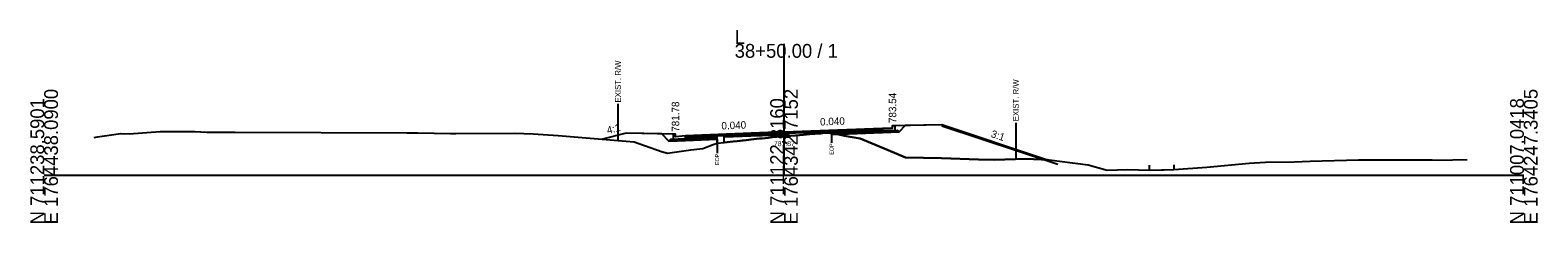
# Model space of a CAD drawing. Extents: x -26 to 5303, y -10 to 9578.
# Drawn here: x 1997.2 to 2302.8, y 8490.3 to 8529.4 of the extents above; entities that cross this region are included whole.
import ezdxf

# ---------------------------------------------------------------- set-up
doc = ezdxf.new("R2010")
doc.units = 0
for name, color, linetype in [('Default', 7, 'Continuous'), ('Exist CMT Pavement', 7, 'Continuous'), ('Exist Cross Section Cell', 7, 'Continuous'), ('Exist XS Ground Line', 7, 'Continuous'), ('Old_Level_10', 7, 'Continuous'), ('Old_Level_3', 7, 'Continuous'), ('Old_Level_4', 7, 'Continuous'), ('Prop CMT Conc Surface', 7, 'Continuous'), ('Prop CMT Concrete Structures', 7, 'Continuous'), ('Prop CMT Pvmt Course 1', 7, 'Continuous'), ('Prop CMT Pvmt Course 1 CG', 7, 'Continuous'), ('Prop CMT Pvmt Course 2', 7, 'Continuous'), ('Prop CMT Pvmt Course 3', 7, 'Continuous'), ('Prop CMT Pvmt Surface', 7, 'Continuous'), ('Prop CMT Slope Grass', 7, 'Continuous'), ('Prop CMT Subgrade Earthwork', 7, 'Continuous'), ('Prop XS Earthwork Shape', 7, 'Continuous'), ('Prop XS EOT Tick Mark', 7, 'Continuous'), ('Prop XS Hydro Elevations', 7, 'Continuous'), ('Prop XS SE Text', 7, 'Continuous'), ('Prop XS Side Slope Text', 7, 'Continuous'), ('Prop XS Wedging', 7, 'Continuous')]:
    doc.layers.add(name, color=color, linetype=linetype)

msp = doc.modelspace()

# ---------------------------------------------------------------- linework, layer by layer
at = {"layer": 'Exist CMT Pavement'}
msp.add_lwpolyline([(2136.43, 8506.48), (2137.88, 8506.63), (2139.72, 8506.82), (2140.51, 8506.9), (2141.5, 8507.02), (2142.31, 8507.11), (2143.27, 8507.21), (2144.44, 8507.34), (2145.05, 8507.4), (2145.55, 8507.45), (2146.83, 8507.58), (2147.68, 8507.68), (2148.48, 8507.76), (2150, 8507.87), (2150.38, 8507.9), (2152.3, 8508.05), (2153.93, 8508.18), (2155.27, 8508.29), (2155.71, 8508.33), (2156.24, 8508.36), (2157.48, 8508.45), (2157.84, 8508.48), (2159.24, 8508.57), (2159.65, 8508.58), (2159.65, 8508.58)], dxfattribs=at)
at = {"layer": 'Exist Cross Section Cell'}
for p, q in [((2150, 8500), (2150, 8526.59)), ((2000, 8500), (2150, 8500)), ((2150, 8500), (2300, 8500))]:
    msp.add_line(p, q, dxfattribs=at)
at = {"layer": 'Exist XS Ground Line'}
msp.add_lwpolyline([(2010.11, 8507.65), (2010.8, 8507.76), (2015.52, 8508.4), (2017.21, 8508.36), (2023.49, 8508.86), (2030.58, 8508.84), (2032.99, 8508.72), (2033.99, 8508.71), (2034.79, 8508.71), (2038.73, 8508.73), (2073.53, 8508.55), (2075.77, 8508.58), (2082.41, 8508.45), (2083.44, 8508.45), (2095.37, 8508.47), (2099.17, 8508.35), (2104.19, 8508.05), (2113.92, 8507.22), (2119.64, 8506.75), (2125.16, 8504.79), (2126.36, 8504.41), (2131.1, 8505.12), (2133.56, 8505.38), (2135.63, 8506.18), (2136.43, 8506.48), (2137.88, 8506.63), (2139.72, 8506.82), (2140.51, 8506.9), (2142.31, 8507.11), (2144.44, 8507.34), (2145.05, 8507.4), (2145.55, 8507.45), (2146.83, 8507.58), (2147.68, 8507.68), (2148.48, 8507.76), (2150, 8507.87), (2150.38, 8507.9), (2152.3, 8508.05), (2155.27, 8508.29), (2155.71, 8508.33), (2156.24, 8508.36), (2157.48, 8508.45), (2157.84, 8508.48), (2159.24, 8508.57), (2159.65, 8508.58), (2162.2, 8507.99), (2165.46, 8507.39), (2171.09, 8505.08), (2174.63, 8503.59), (2181.91, 8503.43), (2189.45, 8503.13), (2192.68, 8503.08), (2199.05, 8503.26), (2203.79, 8503.07), (2211.68, 8502.06), (2215.53, 8501), (2219.74, 8501.15), (2224.01, 8501.02), (2227.08, 8501.07), (2229.04, 8501.1), (2235.72, 8501.59), (2244.32, 8502.44), (2247.61, 8502.6), (2253.45, 8502.68), (2256.65, 8502.84), (2266.46, 8503.1), (2271.74, 8503.06), (2279.33, 8503.07), (2281.4, 8503.07), (2282.66, 8503.05), (2288.49, 8503.16)], dxfattribs=at)
at = {"layer": 'Old_Level_10'}
for p, q in [((2116.34, 8514.42), (2116.34, 8507.02)), ((2197, 8510.61), (2197, 8503.21)), ((2159.65, 8508.58), (2159.65, 8506.53)), ((2136.43, 8506.48), (2136.43, 8504.43))]:
    msp.add_line(p, q, dxfattribs=at)
at = {"layer": 'Old_Level_4'}
msp.add_line((2182, 8510.01), (2205.5, 8502.18), dxfattribs=at)
at = {"layer": 'Prop CMT Conc Surface'}
for points in [[(2128, 8507.78), (2128, 8508.28), (2127.5, 8508.28)], [(2130, 8507.94), (2128, 8507.78)], [(2170, 8509.54), (2172, 8509.54)], [(2172, 8509.54), (2172, 8510.04), (2172.5, 8510.04)]]:
    msp.add_lwpolyline(points, dxfattribs=at)
at = {"layer": 'Prop CMT Concrete Structures'}
for points in [[(2130, 8507.94), (2128, 8507.78), (2128, 8508.28), (2127.5, 8508.28)], [(2127.5, 8508.28), (2127.5, 8507.26), (2130, 8507.36)], [(2130, 8507.36), (2130, 8507.94)], [(2170, 8509.54), (2172, 8509.54), (2172, 8510.04), (2172.5, 8510.04)], [(2172.5, 8510.04), (2172.5, 8509.06), (2170, 8508.96)], [(2170, 8508.96), (2170, 8509.54)]]:
    msp.add_lwpolyline(points, dxfattribs=at)
at = {"layer": 'Prop CMT Pvmt Course 1'}
for points in [[(2150, 8508.74), (2130, 8507.94)], [(2130, 8507.69), (2136.43, 8507.95)], [(2130, 8507.94), (2130, 8507.69)], [(2136.43, 8507.95), (2150, 8508.49)], [(2136.43, 8507.95), (2136.43, 8507.95)], [(2150, 8508.74), (2170, 8509.54)], [(2159.65, 8508.88), (2150, 8508.49)], [(2150, 8508.49), (2150, 8508.74)], [(2150, 8508.49), (2150, 8508.74)], [(2150, 8508.49), (2150, 8508.49), (2150, 8508.49)], [(2150, 8508.49), (2150, 8508.49), (2150, 8508.49)], [(2170, 8509.29), (2159.65, 8508.88)], [(2159.65, 8508.88), (2159.65, 8508.88)], [(2170, 8509.54), (2170, 8509.29)]]:
    msp.add_lwpolyline(points, dxfattribs=at)
at = {"layer": 'Prop CMT Pvmt Course 1 CG'}
for points in [[(2130, 8507.36), (2127, 8507.24), (2126.65, 8506.89)], [(2130, 8507.03), (2130, 8507.36)], [(2170, 8508.96), (2173, 8509.08), (2173.32, 8508.76)], [(2170, 8508.63), (2170, 8508.96)], [(2173.32, 8508.76), (2170, 8508.63)], [(2126.65, 8506.89), (2130, 8507.03)]]:
    msp.add_lwpolyline(points, dxfattribs=at)
at = {"layer": 'Prop CMT Pvmt Course 2'}
for points in [[(2136.43, 8507.95), (2130, 8507.69)], [(2130, 8507.69), (2130, 8507.36)], [(2130, 8507.36), (2136.43, 8507.62)], [(2136.43, 8507.62), (2136.43, 8507.95)], [(2159.65, 8508.88), (2170, 8509.29)], [(2170, 8508.96), (2159.65, 8508.54)], [(2159.65, 8508.54), (2159.65, 8508.88)], [(2170, 8509.29), (2170, 8508.96)]]:
    msp.add_lwpolyline(points, dxfattribs=at)
at = {"layer": 'Prop CMT Pvmt Course 3'}
for points in [[(2136.43, 8507.62), (2130, 8507.36)], [(2130, 8507.36), (2130, 8507.03)], [(2130, 8507.03), (2136.43, 8507.28)], [(2136.43, 8507.28), (2136.43, 8507.62)], [(2159.65, 8508.54), (2170, 8508.96)], [(2170, 8508.63), (2159.65, 8508.21)], [(2159.65, 8508.21), (2159.65, 8508.54)], [(2170, 8508.96), (2170, 8508.63)]]:
    msp.add_lwpolyline(points, dxfattribs=at)
at = {"layer": 'Prop CMT Pvmt Surface'}
for points in [[(2150, 8508.74), (2130, 8507.94)], [(2150, 8508.74), (2170, 8509.54)]]:
    msp.add_lwpolyline(points, dxfattribs=at)
at = {"layer": 'Prop CMT Slope Grass'}
for points in [[(2172.5, 8510.04), (2182, 8510.23), (2203.45, 8503.08)], [(2127.5, 8508.28), (2118, 8508.47), (2113.22, 8507.28)]]:
    msp.add_lwpolyline(points, dxfattribs=at)
at = {"layer": 'Prop CMT Subgrade Earthwork'}
for p, q in [((2136.43, 8507.28), (2136.43, 8506.48)), ((2159.65, 8508.21), (2159.65, 8508.58))]:
    msp.add_line(p, q, dxfattribs=at)
for points in [[(2130, 8507.03), (2126.65, 8506.89), (2125.22, 8508.33)], [(2136.43, 8507.28), (2130, 8507.03)], [(2159.65, 8508.21), (2170, 8508.63)], [(2170, 8508.63), (2173.32, 8508.76), (2174.65, 8510.09)]]:
    msp.add_lwpolyline(points, dxfattribs=at)
at = {"layer": 'Prop XS Earthwork Shape'}
for points in [[(2170, 8508.63), (2173.32, 8508.76), (2174.65, 8510.09), (2182, 8510.23), (2203.45, 8503.08), (2199.05, 8503.26), (2192.68, 8503.08), (2189.45, 8503.13), (2181.91, 8503.43), (2174.63, 8503.59), (2171.09, 8505.08), (2165.46, 8507.39), (2162.2, 8507.99), (2161, 8508.27)], [(2161, 8508.27), (2170, 8508.63), (2173.32, 8508.76), (2174.65, 8510.09), (2182, 8510.23), (2203.45, 8503.08), (2199.05, 8503.26), (2192.68, 8503.08), (2189.45, 8503.13), (2181.91, 8503.43), (2174.63, 8503.59), (2171.09, 8505.08), (2165.46, 8507.39), (2162.2, 8507.99)], [(2125.22, 8508.33), (2118, 8508.47), (2113.22, 8507.28), (2113.92, 8507.22), (2119.64, 8506.75), (2125.16, 8504.79), (2126.36, 8504.41), (2131.1, 8505.12), (2133.56, 8505.38), (2135.63, 8506.18), (2136.43, 8506.48), (2136.43, 8507.28), (2130, 8507.03), (2126.65, 8506.89)], [(2130, 8507.03), (2126.65, 8506.89), (2125.22, 8508.33), (2118, 8508.47), (2113.22, 8507.28), (2113.92, 8507.22), (2119.64, 8506.75), (2125.16, 8504.79), (2126.36, 8504.41), (2131.1, 8505.12), (2133.56, 8505.38), (2135.63, 8506.18), (2136.43, 8506.48), (2136.43, 8507.28)], [(2159.65, 8508.21), (2159.65, 8508.58), (2161, 8508.27)]]:
    msp.add_lwpolyline(points, close=True, dxfattribs=at)
at = {"layer": 'Prop XS EOT Tick Mark'}
for p, q in [((2224.01, 8502.02), (2224.01, 8501.02)), ((2224.01, 8501.02), (2229.04, 8501.1)), ((2229.04, 8502.1), (2229.04, 8501.1))]:
    msp.add_line(p, q, dxfattribs=at)
at = {"layer": 'Prop XS Wedging'}
for points in [[(2137.88, 8506.63), (2137.88, 8508.13), (2139.72, 8508.18), (2140.51, 8508.21), (2141.5, 8508.24), (2142.31, 8508.26), (2143.27, 8508.29), (2144.44, 8508.33), (2145.05, 8508.34), (2145.55, 8508.36), (2146.82, 8508.4), (2147.68, 8508.42), (2148.48, 8508.45), (2150, 8508.49), (2150.38, 8508.5), (2152.3, 8508.56), (2153.93, 8508.61), (2155.27, 8508.65), (2155.7, 8508.66), (2156.24, 8508.68), (2157.48, 8508.72), (2157.85, 8508.73), (2159.24, 8508.77), (2159.65, 8508.78), (2159.65, 8508.58), (2159.24, 8508.57), (2157.85, 8508.48), (2157.48, 8508.45), (2156.24, 8508.36), (2155.7, 8508.33), (2155.27, 8508.29), (2153.93, 8508.18), (2152.3, 8508.05), (2150.38, 8507.9), (2150, 8507.87), (2148.48, 8507.76), (2147.68, 8507.68), (2146.82, 8507.58), (2145.55, 8507.45), (2145.05, 8507.4), (2144.44, 8507.34), (2143.27, 8507.21), (2142.31, 8507.11), (2141.5, 8507.02), (2140.51, 8506.9), (2139.72, 8506.82)], [(2137.88, 8506.63), (2137.88, 8508.13), (2139.72, 8508.18), (2140.51, 8508.21), (2141.5, 8508.24), (2142.31, 8508.26), (2143.27, 8508.29), (2144.44, 8508.33), (2145.05, 8508.34), (2145.55, 8508.36), (2146.82, 8508.4), (2147.68, 8508.42), (2148.48, 8508.45), (2150, 8508.49), (2150.38, 8508.5), (2152.3, 8508.56), (2153.93, 8508.61), (2155.27, 8508.65), (2155.7, 8508.66), (2156.24, 8508.68), (2157.48, 8508.72), (2157.85, 8508.73), (2158.9, 8508.76), (2159.09, 8508.56), (2157.85, 8508.48), (2157.48, 8508.45), (2156.24, 8508.36), (2155.7, 8508.33), (2155.27, 8508.29), (2153.93, 8508.18), (2152.3, 8508.05), (2150.38, 8507.9), (2150, 8507.87), (2148.48, 8507.76), (2147.68, 8507.68), (2146.82, 8507.58), (2145.55, 8507.45), (2145.05, 8507.4), (2144.44, 8507.34), (2143.27, 8507.21), (2142.31, 8507.11), (2141.5, 8507.02), (2140.51, 8506.9), (2139.72, 8506.82)], [(2137.88, 8506.63), (2137.88, 8507.8), (2139.72, 8507.85), (2140.51, 8507.88), (2141.5, 8507.91), (2142.31, 8507.93), (2143.27, 8507.96), (2144.44, 8508), (2145.05, 8508.01), (2145.55, 8508.03), (2146.82, 8508.07), (2147.68, 8508.09), (2148.48, 8508.12), (2150, 8508.16), (2150.38, 8508.17), (2150.93, 8508.19), (2151.17, 8507.96), (2150.38, 8507.9), (2150, 8507.87), (2148.48, 8507.76), (2147.68, 8507.68), (2146.82, 8507.58), (2145.55, 8507.45), (2145.05, 8507.4), (2144.44, 8507.34), (2143.27, 8507.21), (2142.31, 8507.11), (2141.5, 8507.02), (2140.51, 8506.9), (2139.72, 8506.82)]]:
    msp.add_lwpolyline(points, close=True, dxfattribs=at)

# ---------------------------------------------------------------- texts
at = {"layer": 'Default'}
msp.add_text('-', height=0.0001, dxfattribs=at).set_placement((2000, 8500))
at = {"layer": 'Exist Cross Section Cell'}
for s, p in [('L', (2140, 8526.59)), ('38+50.00 / 1', (2140, 8523.79))]:
    msp.add_text(s, height=2.8, dxfattribs=at).set_placement(p)
for s, p in [('E 1764438.0900', (2002.8, 8490)), ('E 1764342.7152', (2152.8, 8490)), ('E 1764247.3405', (2302.8, 8490)), ('N 711238.5901', (2000, 8490)), ('N 711122.8160', (2150, 8490)), ('N 711007.0418', (2300, 8490))]:
    msp.add_text(s, height=2.8, rotation=90, dxfattribs=at).set_placement(p)
at = {"layer": 'Old_Level_10'}
for s, height, p in [('EXIST. R/W', 1.181, (2116.93, 8514.72)), ('EXIST. R/W', 1.181, (2197.59, 8510.91)), ('EOP', 0.787, (2136.83, 8502.03)), ('EOP', 0.787, (2160.04, 8504.13))]:
    msp.add_text(s, height=height, rotation=90, dxfattribs=at).set_placement(p)
at = {"layer": 'Old_Level_3'}
msp.add_text('781.87', height=1, dxfattribs=at).set_placement((2147.96, 8505.87))
at = {"layer": 'Prop XS Hydro Elevations'}
for s, p in [('783.54', (2172.75, 8510.54)), ('781.78', (2128.75, 8508.78))]:
    msp.add_text(s, height=1.5, rotation=90, dxfattribs=at).set_placement(p)
at = {"layer": 'Prop XS SE Text'}
for p in [(2137.34, 8509.24), (2157.34, 8510.04)]:
    msp.add_text('0.040', height=1.5, rotation=2.2906, dxfattribs=at).set_placement(p)
at = {"layer": 'Prop XS Side Slope Text'}
for s, rotation, p in [('4:1', 14.0362, (2114.27, 8508.31)), ('3:1', 341.5651, (2191.83, 8507.75))]:
    msp.add_text(s, height=1.5, rotation=rotation, dxfattribs=at).set_placement(p)

doc.saveas('drawing.dxf')
